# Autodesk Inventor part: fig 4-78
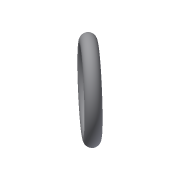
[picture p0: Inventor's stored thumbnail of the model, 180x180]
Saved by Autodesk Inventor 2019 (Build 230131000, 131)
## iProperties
Created: 2012-07
Part Number: fig 4-78
Material: Generic
Document SubType Name: Modeling
Designer: CADCIM
Density: 1 g/cm^3
Appearance: Default
Author: CADCIM
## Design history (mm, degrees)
sketch "Sketch1"
  geometry: L1 (-1.626, -1.876)-(1.626, 1.876); L2 (0, 0)-(7.504, -6.505); C1 r 1.845 at (7.504, -6.505)
  constraints: 4 end point, 1 centre point, 1 midpoint, 1 perpendicular
  dimensions: "d0" = 90 deg dimension on L2.end C1 L1.start L1.end L1 L2.start L2
revolve "Revolution1" sketch "Sketch1" stored, may be unused: angle "d0" = 90 deg
body "Solid1"
